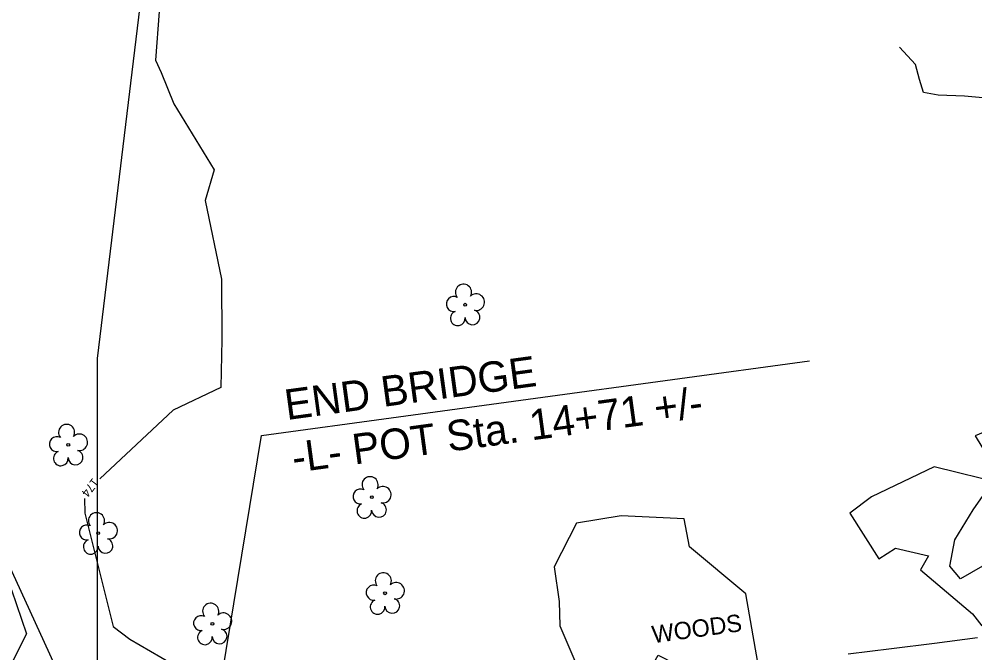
# Model space of a CAD drawing. Extents: x 2086416 to 2115205, y 575507 to 632762.
# Drawn here: x 2111556.7 to 2111776.5, y 581739.2 to 581885 of the extents above; entities that cross this region are included whole.
import ezdxf

# ---------------------------------------------------------------- set-up
doc = ezdxf.new("R2010")
doc.units = 0
for name, color, linetype in [('DTM Contours Major', 7, 'Continuous'), ('DTM Contours Minor', 7, 'Continuous'), ('DTM Contours Minor Text', 7, 'Continuous'), ('Exist Hydro Stream or Body of Water', 7, 'Continuous'), ('Exist Hydrographic FEMA Cross Section', 7, 'Continuous'), ('Exist Hydrographic Stream Bed', 7, 'Continuous'), ('Exist Vegetation Tree CELL', 7, 'Continuous'), ('Exist Vegetation Woods Line', 7, 'Continuous'), ('Exist Vegetation Woods Line Text', 7, 'Continuous'), ('Prop Horizontal Alignment Station Label', 7, 'Continuous')]:
    doc.layers.add(name, color=color, linetype=linetype)

# ---------------------------------------------------------------- blocks, each defined once
blk = doc.blocks.new('EXIST VEGETATION TREE')
at = {"layer": 'Exist Vegetation Tree CELL'}
blk.add_line((0, 0), (0, 0), dxfattribs=at)
blk.add_circle((0, 0), 0.00652, dxfattribs=at)
for centre, radius, start, end in [((-0.0077, 0.0575), 0.0371, 330.1651, 219.7134), ((0.051, 0.0118), 0.038, 257.1011, 134.1999), ((-0.0521, 0.0031), 0.0345, 62.6636, 279.3457), ((-0.0341, -0.0624), 0.0338, 111.5671, 6.231), ((0.0335, -0.058), 0.034, 181.2822, 74.56)]:
    blk.add_arc(centre, radius, start, end, dxfattribs=at)

msp = doc.modelspace()

# ---------------------------------------------------------------- linework, layer by layer
at = {"layer": 'DTM Contours Major'}
for points in [[(2111723.8, 581752.8), (2111710.85, 581763.59), (2111709.62, 581770.1), (2111695.12, 581770.72), (2111684.86, 581769.09), (2111679.76, 581759.06), (2111680.91, 581751.02), (2111681.06, 581745.46), (2111691.54, 581720.93)], [(2111694.31, 581722.46), (2111703.65, 581738.73), (2111728.46, 581726.08), (2111723.8, 581752.8)]]:
    msp.add_lwpolyline(points, dxfattribs=at)
at = {"layer": 'DTM Contours Minor'}
for points in [[(2111608, 581952.88), (2111608.27, 581944.13), (2111600.33, 581942.36), (2111598.01, 581924.92), (2111592.16, 581907.71), (2111589.71, 581900.42), (2111589.76, 581898.02), (2111588.05, 581875.59), (2111589.38, 581872.68), (2111592.31, 581865.53), (2111601.58, 581850.31), (2111599.5, 581843.31), (2111603.29, 581825.19), (2111603.3, 581811.34), (2111603.07, 581800.25), (2111592.15, 581795.07), (2111575.25, 581779.23)], [(2111873.59, 581811.18), (2111858.97, 581807.81), (2111832.44, 581805.87), (2111830.33, 581804.51), (2111803.94, 581800.63), (2111801.15, 581799.34), (2111776.55, 581789.14), (2111783.31, 581778.03), (2111767.14, 581782.05), (2111752.67, 581775.15), (2111747.71, 581771.33), (2111754.42, 581760.88), (2111758.25, 581763.28), (2111765.79, 581761.52), (2111763.95, 581758.36), (2111775.89, 581748.19), (2111778.07, 581745.44)], [(2111571.79, 581774.74), (2111571.85, 581771.39), (2111578.31, 581745.31), (2111582.17, 581742.39), (2111603.57, 581729.99)], [(2111554.95, 581753.72), (2111558.4, 581743.64), (2111555.04, 581736.97)]]:
    msp.add_lwpolyline(points, dxfattribs=at)
at = {"layer": 'Exist Hydro Stream or Body of Water'}
for points in [[(2111812.6, 581817.73), (2111808.22, 581821.88), (2111802.53, 581826.39), (2111797.29, 581830.99), (2111792.48, 581835.64), (2111788.53, 581840.26), (2111786.82, 581845.72), (2111786.48, 581853), (2111785.93, 581858.1), (2111784.22, 581863.27), (2111780.84, 581866.66), (2111774.05, 581867.27), (2111768.06, 581867.49), (2111764.65, 581868.09), (2111763.71, 581871.11), (2111762.78, 581874.58), (2111759.12, 581878.58)], [(2111788.76, 581770.55), (2111784.43, 581763.77), (2111780.8, 581761.15), (2111778.21, 581759.21), (2111773.13, 581756.23), (2111770.68, 581759.14), (2111771.83, 581765.21), (2111776.07, 581772.13), (2111779.43, 581776.99), (2111783.88, 581782.96), (2111786.63, 581784.5), (2111789.27, 581783.19), (2111795.22, 581782.77), (2111801.4, 581783.75), (2111804.55, 581784.97), (2111816.21, 581789.41)]]:
    msp.add_lwpolyline(points, dxfattribs=at)
at = {"layer": 'Exist Hydrographic FEMA Cross Section'}
msp.add_lwpolyline([(2111777.09, 581742.67), (2111767.17, 581741.42), (2111757.26, 581740.16), (2111747.34, 581738.91)], dxfattribs=at)
at = {"layer": 'Exist Hydrographic Stream Bed'}
msp.add_lwpolyline([(2112129.65, 582477.71), (2111835.9, 582368.96), (2111727.15, 582231.15), (2111672.65, 582129.59), (2111610.9, 582009.96), (2111585.65, 581897.53), (2111574.65, 581806.9), (2111574.65, 581727.08), (2111582.9, 581679.52), (2111589.15, 581643.7), (2111621.9, 581589.33), (2111665.4, 581516.77), (2111701.65, 581379.01), (2111737.9, 581248.45), (2111785.15, 581103.39)], dxfattribs=at)
at = {"layer": 'Exist Vegetation Woods Line'}
msp.add_lwpolyline([(2111543, 581784.1), (2111565.77, 581734.52), (2111587.19, 581707.45), (2111708.99, 581713.78), (2111811.99, 581727.73), (2111909.41, 581740.4), (2112007.41, 581746.55), (2112041.96, 581749.79), (2112042.22, 581740.22)], dxfattribs=at)
at = {"layer": 'Prop Horizontal Alignment Station Label'}
for p, q in [((2111612.47, 581789.24), (2111738.42, 581806.43)), ((2111591.21, 581660.22), (2111612.47, 581789.24))]:
    msp.add_line(p, q, dxfattribs=at)

# ---------------------------------------------------------------- block references
at = {"layer": 'Exist Vegetation Tree CELL', "xscale": 50, "yscale": 50}
for p in [(2111659.28, 581819.31), (2111568.02, 581787.07), (2111637.8, 581775.03), (2111574.89, 581766.75), (2111640.85, 581752.93), (2111601.16, 581745.93)]:
    msp.add_blockref('EXIST VEGETATION TREE', p, dxfattribs=at)

# ---------------------------------------------------------------- texts
at = {"layer": 'DTM Contours Minor Text'}
msp.add_text('174', height=2, rotation=232.4306, dxfattribs=at).set_placement((2111573.66, 581779.6))
at = {"layer": 'Exist Vegetation Woods Line Text'}
msp.add_text('WOODS', height=4, rotation=7.771, dxfattribs=at).set_placement((2111702.5, 581741.44))
at = {"layer": 'Prop Horizontal Alignment Station Label'}
for s, p in [('END BRIDGE', (2111618.27, 581792.77)), ('-L- POT Sta. 14+71 +/-  ', (2111619.92, 581780.64))]:
    msp.add_text(s, height=7, rotation=7.771, dxfattribs=at).set_placement(p)

doc.saveas('drawing.dxf')
